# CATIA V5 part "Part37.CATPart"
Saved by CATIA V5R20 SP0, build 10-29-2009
Part number: FA 168700-3
Revision: ANY
Definition: UNKNOWN
Nomenclature: FA 168700-3
Source: Unknown
Bounding box of the stored display mesh (mm): x -3 to 3, y 0 to 4.95, z -3.464 to 3.464
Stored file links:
  C:\Users\Utente\Desktop\IO LAVORO\3D X SITO CF\CUMSA\3D files FA\FA 2007SF\Part37.CATPart

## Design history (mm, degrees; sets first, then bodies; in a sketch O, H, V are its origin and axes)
Body1 "Cortar-Extruir3" (main body)
  Solid1: solid without history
